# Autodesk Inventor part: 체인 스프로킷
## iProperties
Created: 2014-07
Part Number: 체인 스프로킷
Material: Steel
Document SubType Name: Modeling
Designer: KYOUNG IL JANG
Density: 1 g/cm^3
CustomPartVersion: 1
Company: 한국ATC센터
Author: KYOUNG IL JANG
